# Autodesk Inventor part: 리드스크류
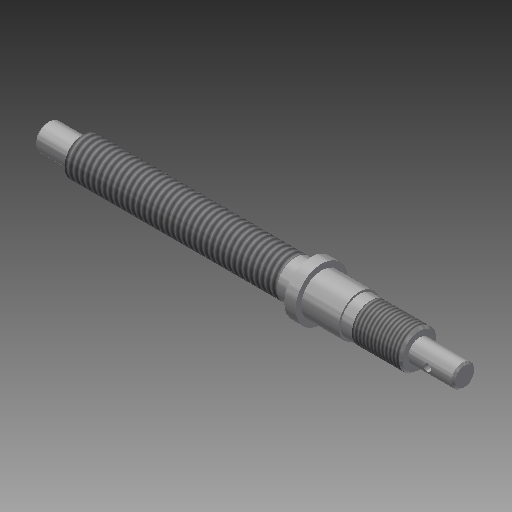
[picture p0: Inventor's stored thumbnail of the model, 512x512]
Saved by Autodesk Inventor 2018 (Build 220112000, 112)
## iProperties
Created: 2020-03
Part Number: 리드스크류
Material: 강철, 연강
Document SubType Name: Modeling
Designer: mduedu
Density: 7.86 g/cm^3
Appearance: 강철
Mass: 63.7782 g
Surface Area: 36.2706 cm^2
Volume: 8.11427 cm^3
Author: mduedu
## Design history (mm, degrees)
sketch "스케치1"
  geometry: L1 (0, 0)-(9, 0); L2 (9, 0)-(9, 3.5); L3 (9, 3.5)-(0, 3.5); L4 (0, 3.5)-(0, 0); L5 (9, 0)-(70, 0); L6 (70, 0)-(70, 5); L7 (70, 5)-(9, 5); L8 (9, 5)-(9, 0); L9 (70, 0)-(73, 0); L10 (73, 0)-(73, 7); L11 (73, 7)-(70, 7); L12 (70, 7)-(70, 0); L13 (73, 0)-(83, 0); L14 (83, 0)-(83, 5.5); L15 (83, 5.5)-(73, 5.5); L16 (73, 5.5)-(73, 0); L17 (83, 0)-(99, 0); L18 (99, 0)-(99, 5); L19 (99, 5)-(83, 5); L20 (83, 5)-(83, 0); L21 (99, 0)-(111, 0); L22 (111, 0)-(111, 3); L23 (111, 3)-(99, 3); L24 (99, 3)-(99, 0)
  constraints: 48 end point, 12 parallel, 6 horizontal, 6 perpendicular
  dimensions: "d0" = 61 distance of L6.end L7.end; "d2" = 9 distance of L2.end L3.end; "d3" = 3 distance of L10.end L11.end; "d4" = 10 distance of L14.end L15.end; "d5" = 16 distance of L18.end L19.end; "d6" = 12 distance of L22.end L23.end; "d7" = 7 diameter of L3 L1; "d8" = 10 diameter of L7 L5; "d9" = 14 diameter of L11 L9; "d10" = 11 diameter of L15 L13; "d11" = 10 diameter of L19 L17; "d12" = 6 diameter of L23 L21
revolve "회전1" sketch "스케치1" stored, may be unused: angle "d13" = 90 deg
feature "스레드1" dims "d14" = 57, "d15" = 0
feature "스레드2" dims "d16" = 13, "d17" = 0
chamfer "모따기1" distance "d18" = 0.5; stored, may be unused: second distance "d19" = 2, angle "d20" = 45 deg
sketch "스케치2"
  geometry: L1 (111, 2.5)-(111, -2.5) reference; C1 r 1 at (104, 0); 1 further point
  constraints: 1 centre point, 1 horizontal alignment
  dimensions: "d21" = 2 diameter of C1; "d22" = 7 distance from line of C1.centre L1
extrude "돌출1" cut sketch "스케치2" extent not by distance; stored distance "d23" = 10; taper "d24" = 0 deg
node "솔리드1"
